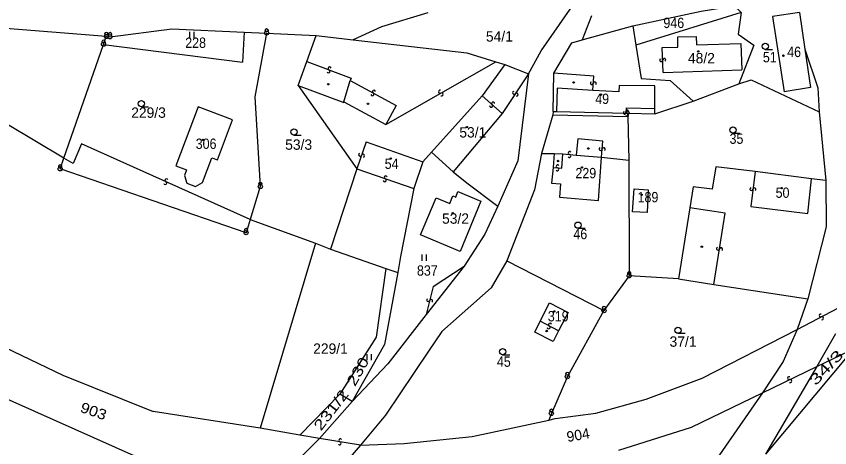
# Model space of a CAD drawing. Extents: x -680102 to -677253, y -1007548 to -1006096.
# Drawn here: x -679953.4 to -679757, y -1007313.8 to -1007209.6 of the extents above; entities that cross this region are included whole.
import ezdxf
from ezdxf.enums import TextEntityAlignment as Align

# ---------------------------------------------------------------- set-up
doc = ezdxf.new("R2010")
doc.units = 0
for name, color, linetype, lineweight in [('1', 7, 'Continuous', 25), ('24', 7, 'Continuous', 25), ('25', 7, 'Continuous', 25), ('4', 7, 'Continuous', 25)]:
    doc.layers.add(name, color=color, linetype=linetype, lineweight=lineweight)
doc.layers.add('18', color=7, linetype='Continuous')
doc.layers.add('19', color=7, linetype='Continuous')

msp = doc.modelspace()

# ---------------------------------------------------------------- linework, layer by layer
at = {"layer": '1'}
for p, q in [((-679853.99, -1007208.8), (-679865.24, -1007212.16)), ((-679778.42, -1007208.71), (-679803.8, -1007216.62)), ((-679764.29, -1007208.71), (-679770.85, -1007209.71)), ((-679764.29, -1007208.71), (-679763.02, -1007217.57)), ((-679814.54, -1007209.57), (-679816.78, -1007215.35)), ((-679770.85, -1007209.71), (-679768.03, -1007227.9)), ((-679931.64, -1007214.53), (-679964.05, -1007211.96)), ((-679865.24, -1007212.16), (-679872.03, -1007215.3)), ((-679804.53, -1007211.96), (-679803.8, -1007216.62)), ((-679932.29, -1007216.42), (-679931.64, -1007214.53)), ((-679898.32, -1007213.45), (-679898.78, -1007220.75)), ((-679892.93, -1007213.7), (-679880.95, -1007214.27)), ((-679932.29, -1007216.42), (-679898.78, -1007220.75)), ((-679823.61, -1007223.41), (-679819.24, -1007216.03)), ((-679803.8, -1007216.62), (-679802.55, -1007224.64)), ((-679775.35, -1007216.63), (-679778.95, -1007225.98)), ((-679763.02, -1007217.57), (-679761.66, -1007226.81)), ((-679763.02, -1007217.57), (-679759.88, -1007226.89)), ((-679835.43, -1007221.28), (-679840.91, -1007228.82)), ((-679829.74, -1007223.55), (-679832.27, -1007244.54)), ((-679823.81, -1007232.65), (-679823.61, -1007223.41)), ((-679802.55, -1007224.64), (-679795.5, -1007225.18)), ((-679885.35, -1007226.35), (-679871.16, -1007246.49)), ((-679795.5, -1007225.18), (-679790, -1007230.15)), ((-679776.02, -1007224.96), (-679759.53, -1007232.74)), ((-679761.66, -1007226.81), (-679768.03, -1007227.9)), ((-679759.88, -1007226.89), (-679759.53, -1007232.74)), ((-679840.91, -1007228.82), (-679853.15, -1007242.49)), ((-679799.25, -1007233.18), (-679790, -1007230.15)), ((-679823.81, -1007232.65), (-679823.83, -1007233.45)), ((-679759.53, -1007232.74), (-679757.93, -1007249.3)), ((-679823.83, -1007233.45), (-679805.76, -1007233.84)), ((-679805.76, -1007233.84), (-679805.51, -1007244.41)), ((-679853.15, -1007242.49), (-679855.24, -1007244.8)), ((-679853.15, -1007242.49), (-679847.87, -1007247.23)), ((-679826.62, -1007242.77), (-679828.27, -1007251.54)), ((-679897.89, -1007261.91), (-679942.76, -1007246.49)), ((-679871.16, -1007246.49), (-679877.51, -1007265.86)), ((-679855.24, -1007244.8), (-679857.41, -1007251.24)), ((-679847.87, -1007247.23), (-679844.6, -1007249.84)), ((-679844.6, -1007249.84), (-679837.13, -1007255.48)), ((-679757.93, -1007249.3), (-679757.85, -1007260.46)), ((-679857.41, -1007251.24), (-679860.65, -1007267.65)), ((-679828.27, -1007251.54), (-679834.99, -1007268.73)), ((-679757.85, -1007260.46), (-679762.32, -1007277.9)), ((-679881.1, -1007264.45), (-679894.51, -1007309.13)), ((-679834.99, -1007268.73), (-679811.51, -1007280.72)), ((-679864.16, -1007270.51), (-679866.46, -1007287.16)), ((-679805.43, -1007272.32), (-679811.51, -1007280.72)), ((-679793.51, -1007273.02), (-679805.43, -1007272.32)), ((-679784.98, -1007274.38), (-679762.32, -1007277.9)), ((-679762.32, -1007277.9), (-679764.86, -1007285.28)), ((-679854.4, -1007281.68), (-679863.67, -1007293.6)), ((-679811.51, -1007280.72), (-679820.34, -1007296.66)), ((-679787.84, -1007297), (-679764.86, -1007285.28)), ((-679764.86, -1007285.28), (-679768.23, -1007293)), ((-679866.46, -1007287.16), (-679875.26, -1007300.91)), ((-679755.61, -1007286.35), (-679760.1, -1007294.19)), ((-679853.86, -1007290.51), (-679864.24, -1007305.96)), ((-679751.31, -1007289.93), (-679772.5, -1007315.36)), ((-679760.1, -1007294.19), (-679751.31, -1007289.93)), ((-679863.67, -1007293.6), (-679872.32, -1007302.65)), ((-679768.23, -1007293), (-679773.27, -1007300.56)), ((-679760.1, -1007294.19), (-679772.5, -1007315.36)), ((-679942.13, -1007296.31), (-679920.32, -1007305.04)), ((-679875.26, -1007300.91), (-679884.93, -1007310.8)), ((-679773.27, -1007300.56), (-679790.71, -1007325.72)), ((-679790.35, -1007308.83), (-679773.27, -1007300.56)), ((-679872.32, -1007302.65), (-679880.16, -1007311.59)), ((-679894.51, -1007309.13), (-679920.32, -1007305.04)), ((-679864.24, -1007305.96), (-679870.28, -1007313.22)), ((-679884.93, -1007310.8), (-679894.51, -1007309.13)), ((-679807.93, -1007314.43), (-679790.35, -1007308.83)), ((-679880.16, -1007311.59), (-679884.93, -1007310.8))]:
    msp.add_line(p, q, dxfattribs=at)
for points in [[(-679835.43, -1007221.28), (-679829.74, -1007223.55), (-679826.64, -1007218.02), (-679817.82, -1007205.22)], [(-679804.53, -1007211.96), (-679788.01, -1007208.4), (-679780.11, -1007207.15), (-679778.42, -1007208.71)], [(-679778.42, -1007208.71), (-679779.12, -1007213.98), (-679775.35, -1007216.63)], [(-679931.64, -1007214.53), (-679930.73, -1007214.6), (-679915.78, -1007212.64)], [(-679915.78, -1007212.64), (-679898.32, -1007213.45), (-679892.93, -1007213.7)], [(-679819.24, -1007216.03), (-679816.78, -1007215.35), (-679804.53, -1007211.96)], [(-679892.93, -1007213.7), (-679895.78, -1007229.07), (-679894.46, -1007250.76)], [(-679885.35, -1007226.35), (-679883.2, -1007220.6), (-679880.95, -1007214.27)], [(-679880.95, -1007214.27), (-679872.03, -1007215.3), (-679844.57, -1007218.46)], [(-679942.76, -1007246.49), (-679941.86, -1007243.89), (-679932.29, -1007216.42)], [(-679844.57, -1007218.46), (-679837.6, -1007220.61), (-679835.43, -1007221.28)], [(-680035.02, -1007225.06), (-680046.12, -1007230.11), (-680037.24, -1007236.8), (-679998.03, -1007264.71), (-679964.14, -1007285.74), (-679942.13, -1007296.31)], [(-679790, -1007230.15), (-679778.95, -1007225.98), (-679776.02, -1007224.96)], [(-680046.12, -1007230.11), (-680058.82, -1007235.88), (-680050.85, -1007238.38), (-679958.75, -1007300.67), (-679925.02, -1007315.68), (-679907.39, -1007320.2)], [(-679823.83, -1007233.45), (-679826.62, -1007242.77), (-679823.54, -1007242.77)], [(-679805.76, -1007233.84), (-679805.74, -1007233.04), (-679799.25, -1007233.18)], [(-679832.27, -1007244.54), (-679837.13, -1007255.48), (-679840.25, -1007262.27)], [(-679823.54, -1007242.77), (-679823.79, -1007246.14), (-679824.18, -1007249.97), (-679822.01, -1007250.1), (-679822.27, -1007253.32), (-679812.83, -1007254.09), (-679812.1, -1007243.66)], [(-679812.1, -1007243.66), (-679805.51, -1007244.41), (-679805.43, -1007272.32)], [(-679757.93, -1007249.3), (-679761.43, -1007248.86), (-679775.04, -1007247.15), (-679784.51, -1007245.96), (-679785.38, -1007251.35), (-679789.96, -1007250.82), (-679790.76, -1007255.87), (-679793.51, -1007273.02), (-679784.98, -1007274.38)], [(-679894.46, -1007250.76), (-679896.91, -1007258.73), (-679897.89, -1007261.91)], [(-679896.91, -1007258.73), (-679881.1, -1007264.45), (-679877.51, -1007265.86)], [(-679840.25, -1007262.27), (-679845.26, -1007269.96), (-679854.4, -1007281.68)], [(-679877.51, -1007265.86), (-679864.16, -1007270.51), (-679861.28, -1007271.51)], [(-679860.65, -1007267.65), (-679861.28, -1007271.51), (-679864.52, -1007288.86)], [(-679834.99, -1007268.73), (-679838.74, -1007275.25), (-679850.67, -1007285.73), (-679853.86, -1007290.51)], [(-679864.52, -1007288.86), (-679872.32, -1007302.65), (-679875.26, -1007300.91)], [(-679820.34, -1007296.66), (-679824.2, -1007305.55), (-679824.84, -1007307.14)], [(-679823.27, -1007306.8), (-679813.47, -1007305.51), (-679801.31, -1007302.13), (-679787.84, -1007297)], [(-679843.3, -1007311.1), (-679824.84, -1007307.14), (-679823.27, -1007306.8)], [(-679870.28, -1007313.22), (-679859.7, -1007312.78), (-679843.3, -1007311.1)], [(-679880.16, -1007311.59), (-679889.19, -1007320.71), (-679896.47, -1007330.3)], [(-679870.28, -1007313.22), (-679877.41, -1007321.47), (-679890.39, -1007336.48)]]:
    msp.add_lwpolyline(points, dxfattribs=at)
for points in [[(-679901.15, -1007234.64), (-679909.45, -1007231.5), (-679914.87, -1007245.76), (-679912.26, -1007246.74), (-679912.78, -1007248.13), (-679912.17, -1007249.98), (-679910.13, -1007250.76), (-679908.43, -1007249.79), (-679906.14, -1007243.79), (-679904.82, -1007244.27)], [(-679846.75, -1007251.99), (-679841.22, -1007254.28), (-679846.19, -1007266.46), (-679855.81, -1007262.45), (-679852.03, -1007253.45), (-679848.74, -1007254.82), (-679847.99, -1007253.01), (-679847.29, -1007253.29)], [(-679804.19, -1007251.3), (-679800.82, -1007251.53), (-679801.09, -1007257.03), (-679804.6, -1007256.9)], [(-679824.63, -1007278.84), (-679820.19, -1007281.13), (-679822.49, -1007285.58), (-679823.8, -1007288.14), (-679828.23, -1007285.89), (-679826.92, -1007283.27)]]:
    msp.add_lwpolyline(points, close=True, dxfattribs=at)
at = {"layer": '24'}
for centre, radius in [((-679931.64, -1007214.53), 0.5), ((-679931.64, -1007214.53), 0.022), ((-679930.73, -1007214.6), 0.5), ((-679930.73, -1007214.6), 0.022), ((-679892.93, -1007213.7), 0.5), ((-679892.93, -1007213.7), 0.022), ((-679932.29, -1007216.42), 0.5), ((-679932.29, -1007216.42), 0.022), ((-679942.76, -1007246.49), 0.5), ((-679942.76, -1007246.49), 0.022), ((-679894.46, -1007250.76), 0.5), ((-679894.46, -1007250.76), 0.022), ((-679897.89, -1007261.91), 0.5), ((-679897.89, -1007261.91), 0.022), ((-679805.43, -1007272.32), 0.5), ((-679805.43, -1007272.32), 0.022), ((-679811.51, -1007280.72), 0.5), ((-679811.51, -1007280.72), 0.022), ((-679820.34, -1007296.66), 0.5), ((-679820.34, -1007296.66), 0.022), ((-679824.2, -1007305.55), 0.5), ((-679824.2, -1007305.55), 0.022)]:
    msp.add_circle(centre, radius, dxfattribs=at)
for centre in [(-679892.931, -1007213.137), (-679931.641, -1007213.967), (-679930.731, -1007214.037), (-679932.291, -1007215.857), (-679942.761, -1007245.927), (-679894.461, -1007250.197), (-679897.891, -1007261.347), (-679805.431, -1007271.757), (-679811.511, -1007280.157), (-679820.341, -1007296.097), (-679824.201, -1007304.987)]:
    msp.add_arc(centre, 0.437, 328.35109, 209.97456, dxfattribs=at)
at = {"layer": '25'}
for p, q in [((-679911.427, -1007214.935), (-679911.427, -1007213.435)), ((-679910.393, -1007214.935), (-679910.393, -1007213.435)), ((-679772.57, -1007217.63), (-679770.82, -1007217.63)), ((-679923.16, -1007231.51), (-679921.41, -1007231.51)), ((-679886.34, -1007238.35), (-679884.59, -1007238.35)), ((-679780.38, -1007237.84), (-679778.63, -1007237.84)), ((-679817.77, -1007260.83), (-679816.02, -1007260.83)), ((-679855.367, -1007268.705), (-679855.367, -1007267.205)), ((-679854.333, -1007268.705), (-679854.333, -1007267.205)), ((-679793.66, -1007286.2), (-679791.91, -1007286.2)), ((-679868.647, -1007292.695), (-679868.647, -1007291.195)), ((-679867.613, -1007292.695), (-679867.613, -1007291.195)), ((-679835.97, -1007291.38), (-679834.22, -1007291.38))]:
    msp.add_line(p, q, dxfattribs=at)
for centre, radius in [((-679772.57, -1007216.88), 0.75), ((-679788.75, -1007218.14), 0.175), ((-679768.19, -1007219.16), 0.175), ((-679878.04, -1007226.06), 0.175), ((-679818.83, -1007225.61), 0.175), ((-679812.2, -1007228.56), 0.175), ((-679923.16, -1007230.76), 0.75), ((-679868.46, -1007230.77), 0.175), ((-679844.6, -1007236.4), 0.175), ((-679780.38, -1007237.09), 0.75), ((-679886.34, -1007237.6), 0.75), ((-679908.27, -1007239.49), 0.175), ((-679815.28, -1007241.57), 0.175), ((-679862.96, -1007244), 0.175), ((-679822.58, -1007244.59), 0.175), ((-679816.84, -1007246.14), 0.175), ((-679768.61, -1007251.13), 0.175), ((-679802.44, -1007252.75), 0.175), ((-679848.01, -1007257.21), 0.175), ((-679817.77, -1007260.08), 0.75), ((-679787.89, -1007265.31), 0.175), ((-679823.51, -1007280.91), 0.175), ((-679825.34, -1007285.64), 0.175), ((-679793.66, -1007285.45), 0.75), ((-679835.97, -1007290.63), 0.75)]:
    msp.add_circle(centre, radius, dxfattribs=at)
for centre, radius, start, end in [((-679797.697, -1007220.209), 0.367, 129.26926, 1.4048), ((-679796.961, -1007220.193), 0.369, 309.26996, 181.34459), ((-679877.994, -1007222.943), 0.368, 196.7157, 68.85395), ((-679877.728, -1007222.257), 0.367, 16.53736, 248.95327), ((-679814.447, -1007225.786), 0.367, 124.22835, 356.2613), ((-679813.713, -1007225.835), 0.368, 304.16671, 176.24666), ((-679867.389, -1007228.492), 0.368, 188.90137, 60.70431), ((-679867.032, -1007227.848), 0.368, 8.60721, 241.06832), ((-679851.07, -1007227.859), 0.368, 67.11146, 299.28381), ((-679850.711, -1007228.503), 0.369, 246.84418, 119.01257), ((-679833.225, -1007228.143), 0.369, 93.73214, 325.83829), ((-679832.615, -1007228.555), 0.368, 273.56762, 146.09489), ((-679838.26, -1007230.709), 0.368, 355.17459, 227.31284), ((-679838.759, -1007231.251), 0.368, 175.13458, 47.42298), ((-679806.478, -1007232.927), 0.368, 127.54535, 359.53578), ((-679805.917, -1007232.673), 0.368, 35.36341, 267.97343), ((-679805.741, -1007232.934), 0.369, 307.40054, 179.38323), ((-679805.944, -1007233.408), 0.368, 215.62962, 87.82487), ((-679819.794, -1007242.664), 0.367, 31.92123, 264.38452), ((-679812.296, -1007241.673), 0.367, 122.19234, 354.23023), ((-679811.563, -1007241.748), 0.369, 302.13965, 174.09278), ((-679870.367, -1007243.095), 0.369, 108.18991, 339.99173), ((-679869.674, -1007243.343), 0.367, 288.2303, 160.43142), ((-679819.867, -1007243.397), 0.368, 212.13894, 84.09947), ((-679822.757, -1007246.607), 0.368, 212.13894, 84.09947), ((-679822.684, -1007245.874), 0.367, 31.92123, 264.38452), ((-679864.167, -1007248.524), 0.367, 18.06727, 250.43213), ((-679917.414, -1007249.914), 0.368, 192.85985, 65.24714), ((-679917.105, -1007249.246), 0.368, 13.16944, 245.14817), ((-679864.414, -1007249.217), 0.369, 198.33825, 70.33914), ((-679775.915, -1007251.331), 0.369, 120.45863, 352.12371), ((-679775.186, -1007251.427), 0.367, 300.28127, 172.644), ((-679783.972, -1007265.74), 0.367, 118.32198, 350.59181), ((-679783.247, -1007265.863), 0.369, 298.37689, 170.54843), ((-679853.937, -1007278.179), 0.368, 113.7105, 345.70248), ((-679853.224, -1007278.359), 0.367, 293.64207, 165.96508), ((-679759.219, -1007281.893), 0.368, 64.86671, 297.33317), ((-679824.525, -1007284.106), 0.368, 9.69261, 241.8546), ((-679758.882, -1007282.548), 0.369, 245.1726, 117.40402), ((-679824.873, -1007284.755), 0.368, 189.56141, 61.97378), ((-679766.848, -1007297.048), 0.367, 63.43654, 295.45229), ((-679766.534, -1007297.714), 0.369, 243.36727, 115.31542), ((-679875.282, -1007312.772), 0.367, 207.91628, 80.28185), ((-679875.156, -1007312.047), 0.368, 28.02694, 260.0031)]:
    msp.add_arc(centre, radius, start, end, dxfattribs=at)
at = {"layer": '4'}
for p, q in [((-679864.17, -1007235.75), (-679837.6, -1007220.61)), ((-679797.24, -1007223.18), (-679778.27, -1007222.59)), ((-679829.74, -1007223.55), (-679836.1, -1007233.14)), ((-679813.99, -1007224.07), (-679823.61, -1007223.41)), ((-679814.18, -1007227.54), (-679813.99, -1007224.07)), ((-679799.24, -1007231.92), (-679799.21, -1007226.43)), ((-679836.1, -1007233.14), (-679840.91, -1007228.82)), ((-679822.83, -1007227.02), (-679823, -1007232.67)), ((-679814.18, -1007227.54), (-679822.83, -1007227.02)), ((-679807.9, -1007227.92), (-679814.18, -1007227.54)), ((-679874.28, -1007230.32), (-679864.17, -1007235.75)), ((-679799.25, -1007233.18), (-679799.24, -1007231.92)), ((-679836.1, -1007233.14), (-679847.87, -1007247.23)), ((-679806.11, -1007233.03), (-679805.74, -1007233.04)), ((-679868.88, -1007239.94), (-679871.16, -1007246.49)), ((-679868.88, -1007239.94), (-679855.24, -1007244.8)), ((-679823.54, -1007242.77), (-679821.42, -1007242.89)), ((-679821.42, -1007242.89), (-679818.25, -1007243.17)), ((-679818.25, -1007243.17), (-679812.1, -1007243.66)), ((-679871.16, -1007246.49), (-679857.41, -1007251.24)), ((-679852.76, -1007274.86), (-679845.26, -1007269.96)), ((-679852.76, -1007274.86), (-679854.4, -1007281.68)), ((-679764.86, -1007285.28), (-679753.24, -1007279.15)), ((-679822.49, -1007285.58), (-679826.92, -1007283.27)), ((-679773.27, -1007300.56), (-679760.1, -1007294.19)), ((-679870.28, -1007313.22), (-679880.16, -1007311.59))]:
    msp.add_line(p, q, dxfattribs=at)
for points in [[(-679896.91, -1007258.73), (-679937.6, -1007240.42), (-679939.65, -1007245.21), (-679941.86, -1007243.89), (-679990.92, -1007214.64)], [(-679797.24, -1007223.18), (-679797.43, -1007217.22), (-679793.67, -1007217.12), (-679793.72, -1007214.62), (-679789.22, -1007214.54), (-679789.18, -1007216.57), (-679778.49, -1007216.23), (-679778.27, -1007222.59)], [(-679883.2, -1007220.6), (-679872.53, -1007224.59), (-679872.74, -1007225.19), (-679861.69, -1007231.15), (-679864.17, -1007235.75)], [(-679885.35, -1007226.35), (-679874.32, -1007230.47), (-679874.28, -1007230.32), (-679872.74, -1007225.19)], [(-679799.21, -1007226.43), (-679807.88, -1007226.36), (-679807.9, -1007227.92)], [(-679823.81, -1007232.65), (-679823, -1007232.67), (-679806.11, -1007233.03)], [(-679806.11, -1007233.03), (-679806.11, -1007232.83), (-679806.09, -1007231.77), (-679799.24, -1007231.92)], [(-679812.1, -1007243.66), (-679811.75, -1007239.76), (-679817.84, -1007239.22), (-679818.25, -1007243.17)], [(-679823.79, -1007246.14), (-679821.65, -1007246.33), (-679821.42, -1007242.89)], [(-679775.04, -1007247.15), (-679776.06, -1007255.6), (-679762.34, -1007257.26), (-679761.43, -1007248.86)], [(-679784.98, -1007274.38), (-679782.25, -1007257.22), (-679790.76, -1007255.87)]]:
    msp.add_lwpolyline(points, dxfattribs=at)

# ---------------------------------------------------------------- texts
at = {"layer": '18', "width": 0.9}
msp.add_text('946', height=2.5, dxfattribs=at).set_placement((-679794.66, -1007212.49), align=Align.CENTER)
at = {"layer": '18'}
msp.add_text('54/1', height=2.5, dxfattribs=at).set_placement((-679836.75, -1007215.76), align=Align.CENTER)
at = {"layer": '18', "width": 0.9}
for s, p in [('228', (-679912.58, -1007217.28)), ('51', (-679773.15, -1007220.77)), ('35', (-679781.2, -1007240.45)), ('46', (-679818.9, -1007263.47)), ('837', (-679856.65, -1007272.28)), ('45', (-679837.36, -1007294.28))]:
    msp.add_text(s, height=2.5, dxfattribs=at).set_placement(p)
at = {"layer": '18'}
for s, p in [('229/3', (-679925.62, -1007234.16)), ('53/3', (-679888.45, -1007241.88)), ('37/1', (-679795.68, -1007289.44)), ('229/1', (-679881.7, -1007291.14))]:
    msp.add_text(s, height=2.5, dxfattribs=at).set_placement(p)
for s, rotation, width, p in [('34/3', 47, 1.55, (-679760.399, -1007298.998)), ('230', 61, 1.3, (-679871.597, -1007299.189)), ('231/2', 52.5, 1.35, (-679879.806, -1007309.92)), ('903', 340.803, 1.15, (-679938.136, -1007305.107))]:
    msp.add_text(s, height=2.5, rotation=rotation, dxfattribs=dict(at, width=width)).set_placement(p)
msp.add_text('904', height=2.5, rotation=10, dxfattribs=at).set_placement((-679820.278, -1007312.459))
at = {"layer": '19', "width": 0.9}
for s, p in [('46', (-679767.29, -1007219.5)), ('49', (-679813.62, -1007230.82)), ('306', (-679910.05, -1007241.67)), ('54', (-679864.44, -1007246.5)), ('229', (-679818.4, -1007248.76)), ('189', (-679803.4, -1007254.56)), ('50', (-679770.08, -1007253.49)), ('319', (-679825.06, -1007283.32))]:
    msp.add_text(s, height=2.5, dxfattribs=at).set_placement(p)
at = {"layer": '19'}
for s, p in [('48/2', (-679791.24, -1007221.01)), ('53/1', (-679846.42, -1007238.92)), ('53/2', (-679850.59, -1007259.74))]:
    msp.add_text(s, height=2.5, dxfattribs=at).set_placement(p)

doc.saveas('drawing.dxf')
